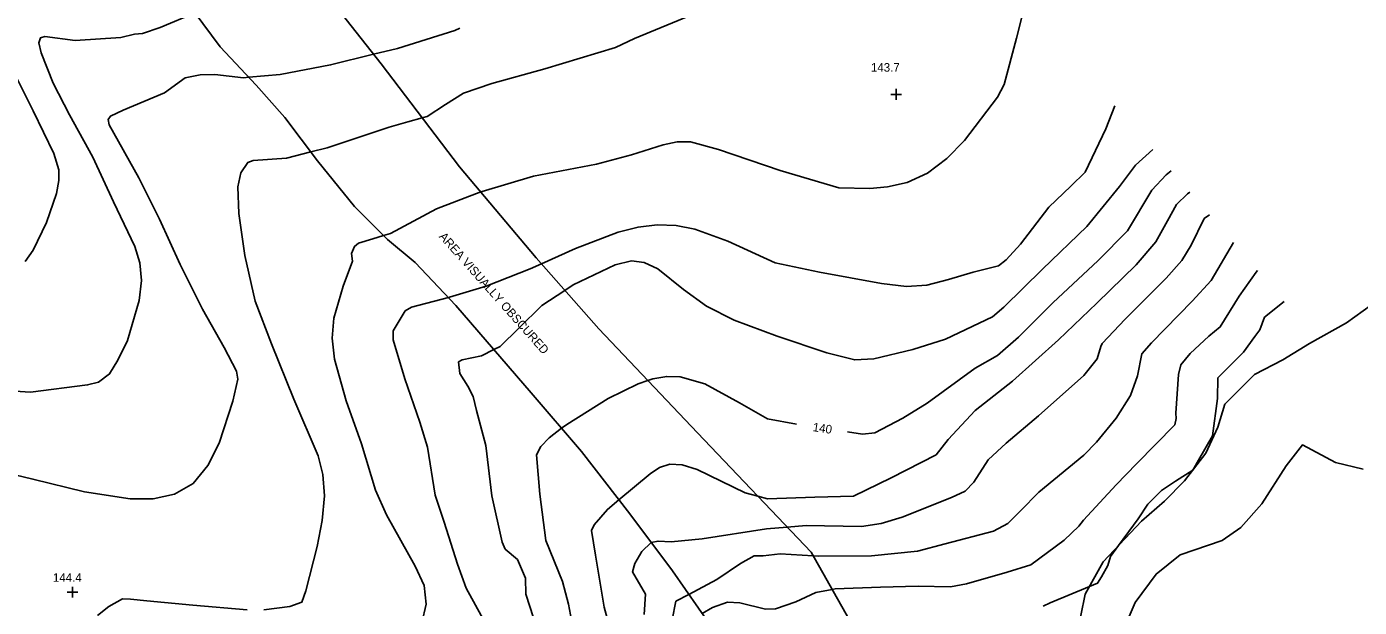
# Model space of a CAD drawing. Extents: x 1475150 to 2003689, y 770235 to 1112803.
# Drawn here: x 2000704.8 to 2001014.7, y 773387.6 to 773522.7 of the extents above; entities that cross this region are included whole.
import ezdxf

# ---------------------------------------------------------------- set-up
doc = ezdxf.new("R2010")
doc.units = 0
for name, color, linetype in [('RD_DTM_Major1', 7, 'Continuous'), ('RD_DTM_Major1_Lbl', 7, 'Continuous'), ('RD_DTM_Major2', 7, 'Continuous'), ('RD_DTM_Minor1', 7, 'Continuous'), ('RD_DTM_Minor2', 7, 'Continuous'), ('RD_DTM_Obscure', 7, 'Continuous'), ('RD_DTM_Spot_Elev', 7, 'Continuous'), ('RD_TX_Misc1', 7, 'Continuous')]:
    doc.layers.add(name, color=color, linetype=linetype)

msp = doc.modelspace()

# ---------------------------------------------------------------- linework, layer by layer
at = {"layer": 'RD_DTM_Major1'}
for points in [[(2000785.51, 773516.28), (2000791.06, 773517.64), (2000804.37, 773521.83), (2000805.58, 773522.32)], [(2000702.1, 773418.42), (2000706.28, 773417.44), (2000718.32, 773414.49), (2000728.94, 773412.87), (2000734.27, 773412.87), (2000739.24, 773413.93), (2000743.55, 773416.45), (2000746.98, 773420.64), (2000749.59, 773425.81), (2000752.81, 773435.55), (2000753.94, 773440.71), (2000753.6, 773442.53), (2000750.74, 773448.04), (2000745.72, 773456.96), (2000740.5, 773467.4), (2000735.74, 773477.9), (2000730.91, 773487.54), (2000724.02, 773499.89), (2000723.81, 773501.08), (2000724.3, 773501.87), (2000727.31, 773503.29), (2000736.9, 773507.29), (2000741.67, 773510.81), (2000745.21, 773511.52), (2000748.59, 773511.57), (2000755.23, 773510.84), (2000756.51, 773510.95)], [(2000895.7, 773428.41), (2000899.23, 773427.88), (2000902.09, 773428.24), (2000908.61, 773431.66), (2000914.21, 773435.12), (2000925.38, 773443.27), (2000930.62, 773446.23), (2000935.47, 773450.49), (2000943.43, 773458.48), (2000954.04, 773468.32), (2000960.86, 773475.19), (2000966.5, 773484.64), (2000969.78, 773488.25), (2000970.99, 773489.17)], [(2000958.75, 773402.01), (2000963.28, 773408.23), (2000965.56, 773411.62), (2000968.77, 773414.77), (2000971.99, 773416.96), (2000976.01, 773419.53), (2000977.34, 773421.82), (2000980.58, 773427.49), (2000981.77, 773436.19), (2000981.86, 773441.01), (2000987.83, 773446.96), (2000990.44, 773450.65), (2000991.59, 773452.16), (2000992.7, 773455.09), (2000997.28, 773458.79)], [(2000849.3, 773440.39), (2000850.43, 773440.76), (2000853.69, 773441.33), (2000856.77, 773441.26), (2000862.53, 773439.58), (2000870.63, 773435.19), (2000877.09, 773431.45), (2000883.83, 773430.21)], [(2000832.9, 773377.17), (2000830.83, 773388.35), (2000829.46, 773393.66), (2000825.53, 773403.17), (2000824.19, 773413.97), (2000823.42, 773423.07), (2000824.41, 773425.01), (2000826.32, 773427.03), (2000829.24, 773429.27)], [(2000941.18, 773387.91), (2000942.85, 773388.66), (2000951.96, 773392.46)]]:
    msp.add_lwpolyline(points, dxfattribs=at)
at = {"layer": 'RD_DTM_Major2'}
for points in [[(2000756.51, 773510.95), (2000763.82, 773511.61), (2000775.51, 773513.82), (2000785.51, 773516.28)], [(2000829.24, 773429.27), (2000830.42, 773430.18), (2000840.04, 773436.23), (2000847.03, 773439.64), (2000849.3, 773440.39)], [(2000951.96, 773392.46), (2000953.87, 773393.25), (2000954.75, 773394.72), (2000956.26, 773397.37), (2000956.89, 773399.46), (2000958.75, 773402.01)]]:
    msp.add_lwpolyline(points, dxfattribs=at)
at = {"layer": 'RD_DTM_Minor1'}
for points in [[(2000796.83, 773501.47), (2000797.99, 773501.8), (2000802.24, 773504.61), (2000806.43, 773507.27), (2000813.01, 773509.48), (2000825.34, 773512.91), (2000841.79, 773517.87), (2000846.16, 773519.97), (2000859.89, 773525.58), (2000876.35, 773527.93), (2000883.99, 773530.28), (2000891.05, 773536.16), (2000893.99, 773539.1), (2000901.66, 773544.65), (2000905.31, 773546.23), (2000910.32, 773550.2), (2000914.62, 773554.32)], [(2000810.42, 773484.25), (2000810.76, 773484.38), (2000822.72, 773487.9), (2000837.33, 773490.72), (2000845.47, 773492.85), (2000852.83, 773495.24), (2000856.14, 773495.89), (2000859.21, 773495.88), (2000865.74, 773494.16), (2000880.04, 773489.27), (2000893.7, 773485.23), (2000900.89, 773485.06), (2000905.01, 773485.42), (2000909.62, 773486.48), (2000914.34, 773488.63), (2000918.84, 773492.05), (2000922.89, 773496.21), (2000930.59, 773506.31), (2000932.18, 773509.25), (2000935.05, 773520.02), (2000937.13, 773528.31)], [(2000694.78, 773438.4), (2000705.72, 773437.68), (2000719.02, 773439.35), (2000721.57, 773439.99), (2000724.13, 773441.9), (2000726.04, 773445.1), (2000728.32, 773449.71), (2000731.04, 773459.02), (2000731.58, 773463.62), (2000731.18, 773467.77), (2000730.03, 773471.53), (2000725, 773481.99), (2000720.2, 773492.36), (2000714.78, 773502.21), (2000711.02, 773509.58), (2000708.21, 773516.58), (2000707.71, 773518.94), (2000708.05, 773520.12), (2000709.08, 773520.38), (2000716.09, 773519.49), (2000726.77, 773520.2), (2000729.88, 773520.93), (2000731.78, 773521.09), (2000735.87, 773522.49), (2000743.99, 773525.95)], [(2000704.5, 773468.05), (2000706.35, 773470.68), (2000709.42, 773477.11), (2000711.79, 773483.9), (2000712.36, 773486.89), (2000712.35, 773489.37), (2000711.16, 773493.21), (2000706.36, 773503.16), (2000701.21, 773513.34)], [(2000824.54, 773467.56), (2000832.45, 773471.13), (2000842.38, 773474.93), (2000847, 773476.06), (2000851.48, 773476.59), (2000855.88, 773476.43), (2000860.22, 773475.58), (2000867.89, 773472.79), (2000878.87, 773467.76), (2000889.23, 773465.61), (2000903.65, 773462.92), (2000909.45, 773462.28), (2000914.17, 773462.55), (2000919.24, 773463.86), (2000924.91, 773465.61), (2000930.79, 773467.08), (2000932.63, 773468.45), (2000935.91, 773472.13), (2000942.54, 773480.71), (2000947.65, 773485.59), (2000950.97, 773488.82), (2000955.76, 773498.95), (2000957.91, 773504.29)], [(2000830.01, 773461.35), (2000831.96, 773462.63), (2000841.68, 773467.28), (2000845.45, 773468.21), (2000848.43, 773467.87), (2000851.59, 773466.36), (2000857.61, 773461.59), (2000862.96, 773457.71), (2000869.36, 773454.46), (2000879.36, 773450.71), (2000890.91, 773446.82), (2000897.41, 773445.19), (2000901.84, 773445.45), (2000910.92, 773447.59), (2000918.48, 773450.03), (2000929.47, 773455.21), (2000932.04, 773457.41), (2000941.07, 773466.25), (2000951.38, 773476.25), (2000958.93, 773485.55), (2000962.67, 773490.47), (2000966.69, 773494.15)], [(2000760.02, 773387.06), (2000766.02, 773387.77), (2000768.84, 773388.82), (2000769.72, 773391.47), (2000772.37, 773401.74), (2000773.53, 773407.82), (2000774.07, 773413.59), (2000773.72, 773418.52), (2000772.61, 773422.84), (2000766.97, 773436.02), (2000761.78, 773448.9), (2000758.01, 773458.84), (2000755.6, 773469.47), (2000754.15, 773479.26), (2000753.92, 773485.43), (2000754.62, 773488.68), (2000756.25, 773491.14), (2000757.52, 773491.57), (2000765.28, 773492.15), (2000770.92, 773493.57)], [(2000874.88, 773413.47), (2000877.1, 773412.89), (2000888.12, 773413.23), (2000897.12, 773413.47), (2000905.87, 773417.71), (2000916.36, 773423.11), (2000919.13, 773426.68), (2000925.41, 773433.39), (2000934.05, 773440.25), (2000944.81, 773449.88), (2000953.72, 773458.34), (2000962.84, 773467.31), (2000967.4, 773472.65), (2000970.1, 773477.51), (2000972.25, 773481.35), (2000974.78, 773483.84), (2000975.29, 773484.21)], [(2000881.72, 773406.27), (2000886.09, 773406.62), (2000899, 773406.44), (2000903.55, 773407.1), (2000908.41, 773408.61), (2000919.9, 773413.16), (2000923.08, 773414.65), (2000925.06, 773416.72), (2000928.46, 773421.91), (2000932.62, 773425.81), (2000940.1, 773432.17), (2000950.64, 773441.58), (2000953.77, 773445.46), (2000954.61, 773448.27), (2000954.92, 773449.02), (2000960.29, 773454.63), (2000969.81, 773464.2), (2000973.46, 773468.32), (2000975.66, 773471.87), (2000978.63, 773478.06), (2000979.88, 773478.9)], [(2000795.75, 773379.65), (2000797.73, 773388.35), (2000797.24, 773392.68), (2000795.2, 773397.21), (2000788.54, 773409.17), (2000785.98, 773414.88), (2000782.71, 773425.64), (2000779.15, 773435.62), (2000776.45, 773445.32), (2000775.91, 773450.27), (2000776.25, 773454.87), (2000778.42, 773462.33), (2000780.58, 773468.13), (2000780.39, 773469.91), (2000781.06, 773471.57), (2000782, 773472.31), (2000785.31, 773473.35), (2000787.84, 773474.11)], [(2000887.73, 773399.59), (2000888.94, 773399.52), (2000901.3, 773399.57), (2000912.02, 773400.7), (2000918.42, 773402.39), (2000929.66, 773405.37), (2000932.97, 773407.12), (2000935.97, 773410.03), (2000940.24, 773414.43), (2000950.71, 773422.98), (2000953.65, 773426.06), (2000958.21, 773431.66), (2000961.54, 773436.87), (2000963.15, 773441.5), (2000964.18, 773446.62), (2000966.41, 773449.17), (2000975.87, 773458.85), (2000980.25, 773463.69), (2000985.44, 773472.47)], [(2000892.16, 773391.76), (2000892.86, 773391.88), (2000903.36, 773392.34), (2000912.17, 773392.52), (2000919.66, 773392.37), (2000923.4, 773393.1), (2000932.83, 773395.76), (2000938.37, 773397.47), (2000946.11, 773403.26), (2000949.48, 773406.47), (2000950.6, 773407.93), (2000958.18, 773416.08), (2000962.91, 773421.03), (2000971.81, 773430.04), (2000972.15, 773431.53), (2000972.05, 773432.76), (2000972.67, 773441.78), (2000973.22, 773444.04), (2000975.38, 773446.68), (2000979.72, 773450.7), (2000982.4, 773452.87), (2000986.79, 773460.02), (2000990.71, 773465.59), (2000991.07, 773465.97)], [(2000812.73, 773381.74), (2000807.07, 773392.05), (2000805.02, 773397.65), (2000801.92, 773407.39), (2000799.8, 773413.73), (2000798.03, 773424.84), (2000796.29, 773430.66), (2000792.78, 773440.76), (2000790.05, 773449.82), (2000790.08, 773451.98), (2000792.84, 773456.57), (2000794.34, 773457.45), (2000802.92, 773459.69)], [(2000822.73, 773385.16), (2000820.9, 773390.64), (2000820.82, 773394.43), (2000819, 773398.71), (2000816.14, 773401.16), (2000815.45, 773402.81), (2000813.03, 773413.58), (2000811.6, 773425.29), (2000809.46, 773433.37), (2000808.7, 773436.7), (2000807.4, 773439.03), (2000805.57, 773442.01), (2000805.27, 773444.7), (2000806.11, 773445.19), (2000810.61, 773446.14), (2000813.5, 773447.57)], [(2000841.94, 773377.53), (2000839.16, 773387.63), (2000837.14, 773399.75), (2000836.22, 773405.46), (2000836.8, 773406.83), (2000839.9, 773410.41), (2000842.56, 773412.63)], [(2000848.47, 773385.92), (2000848.73, 773390.67), (2000845.73, 773395.91), (2000846.3, 773397.78), (2000847.89, 773400.59), (2000850.07, 773402.72)], [(2000721.32, 773385.74), (2000723.94, 773387.8), (2000727.12, 773389.6), (2000728.97, 773389.53), (2000732.8, 773389.09), (2000743.52, 773388.12), (2000756.13, 773387.01)], [(2000854.97, 773384.73), (2000855.81, 773389.03), (2000858.82, 773390.62)]]:
    msp.add_lwpolyline(points, dxfattribs=at)
at = {"layer": 'RD_DTM_Minor2'}
for points in [[(2000770.92, 773493.57), (2000774.75, 773494.54), (2000789.15, 773499.35), (2000793.44, 773500.54), (2000796.83, 773501.47)], [(2000787.84, 773474.11), (2000789.44, 773474.6), (2000800.14, 773480.29), (2000810.42, 773484.25)], [(2000802.92, 773459.69), (2000803.13, 773459.74), (2000811.7, 773462.33), (2000821.9, 773466.36), (2000824.54, 773467.56)], [(2000813.5, 773447.57), (2000814.95, 773448.29), (2000819.28, 773452.54), (2000824.67, 773457.8), (2000830.01, 773461.35)], [(2000842.56, 773412.63), (2000849.83, 773418.7), (2000852.03, 773420.15), (2000854.43, 773420.93), (2000857.29, 773420.8), (2000860.78, 773419.65), (2000871.93, 773414.23), (2000874.88, 773413.47)], [(2000850.07, 773402.72), (2000850.08, 773402.73), (2000851.68, 773403.04), (2000854.74, 773402.88), (2000861.93, 773403.58), (2000876.9, 773405.88), (2000881.72, 773406.27)], [(2000858.82, 773390.62), (2000865.36, 773394.09), (2000870.84, 773397.82), (2000874.02, 773399.59), (2000876.13, 773399.59), (2000880.06, 773400.04), (2000887.73, 773399.59)], [(2000861.92, 773386.16), (2000864.34, 773387.58), (2000867.83, 773388.78), (2000870.65, 773388.67), (2000876.64, 773387.22), (2000878.94, 773387.25), (2000883.67, 773388.93), (2000888.33, 773391.05), (2000892.16, 773391.76)]]:
    msp.add_lwpolyline(points, dxfattribs=at)
at = {"layer": 'RD_DTM_Obscure'}
for points in [[(2000770.7, 773535.19), (2000787.27, 773514.02), (2000805.49, 773490.1), (2000823.32, 773468.94), (2000837.91, 773452.39), (2000860.86, 773428.21), (2000887.24, 773400.47), (2000909.35, 773361.29), (2000917.09, 773351.66), (2000922.72, 773342.58), (2000923.12, 773337.49), (2000915.94, 773326.73)], [(2000915.94, 773326.73), (2000890.4, 773351.79), (2000875.77, 773367.34), (2000864.07, 773383.05), (2000855.01, 773396.12), (2000845.08, 773409.36), (2000833.89, 773423.86), (2000822.15, 773437.52), (2000804.67, 773457.85), (2000795.18, 773467.83), (2000788.76, 773473.19), (2000781.06, 773480.88), (2000772.5, 773491.47), (2000764.89, 773501.6), (2000758.24, 773509.11), (2000749.85, 773518.03), (2000739.78, 773531.64)], [(2001019.51, 773459.41), (2001011.77, 773453.84), (2001003.11, 773449.03), (2000996.91, 773445.16), (2000990.36, 773441.79), (2000983.44, 773434.85), (2000981.82, 773429.55), (2000979.07, 773423.47), (2000974.1, 773417.01), (2000969.4, 773412.34), (2000964.07, 773407.67), (2000955.15, 773398.19), (2000950.97, 773390.69), (2000949, 773380.73)], [(2000959.99, 773382.64), (2000962.64, 773388.74), (2000967.49, 773395.36), (2000973.1, 773399.82), (2000982.83, 773403.19), (2000987.16, 773406.18), (2000992.06, 773411.67), (2000997.71, 773420.52), (2001001.5, 773425.41), (2001009.2, 773421.31), (2001015.62, 773419.75)]]:
    msp.add_lwpolyline(points, dxfattribs=at)
at = {"layer": 'RD_DTM_Spot_Elev'}
for p, q in [((2000905.79, 773506.96), (2000908.29, 773506.96)), ((2000907.04, 773505.71), (2000907.04, 773508.21)), ((2000715.5, 773389.92), (2000715.5, 773392.42)), ((2000714.25, 773391.17), (2000716.75, 773391.17))]:
    msp.add_line(p, q, dxfattribs=at)

# ---------------------------------------------------------------- texts
at = {"layer": 'RD_DTM_Major1_Lbl'}
msp.add_text('140', height=2, rotation=351.5246, dxfattribs=at).set_placement((2000887.54, 773428.62))
at = {"layer": 'RD_DTM_Spot_Elev'}
for s, p in [('143.7', (2000901.17, 773512.23)), ('144.4', (2000710.95, 773393.55))]:
    msp.add_text(s, height=2, dxfattribs=at).set_placement(p)
at = {"layer": 'RD_TX_Misc1'}
msp.add_text('AREA VISUALLY OBSCURED', height=2, rotation=311.5526, dxfattribs=at).set_placement((2000800.61, 773473.79))

doc.saveas('drawing.dxf')
